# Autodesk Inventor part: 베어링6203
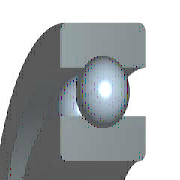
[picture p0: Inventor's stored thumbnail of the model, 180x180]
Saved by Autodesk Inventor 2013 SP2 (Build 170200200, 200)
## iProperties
IsCustomPart: 0
Company: 한국ATC센터
Created: 2014-12
Part Number: 베어링6203
Material: 강, 연강
Description: 깊은 그루브 볼 베어링
Document SubType Name: Modeling
Standard: KS B 2023
Designer: KYOUNG IL JANG
Standards Organization: KS
Language: ko-KR
Size Designation: 6203 - 17 x 40 x 12
Categories: <MemberInstance><Categories><Category DisplayName="샤프트 부품" InternalName="7f7aeb1f-a693-4053-b835-cee3144e0d98" Mnemonic="SHFT"><Category DisplayName="베어링" Inter
Density: 7.86 g/cm^3
Mass: 64.9809 g
Surface Area: 64.3582 cm^2
Volume: 8.26729 cm^3
Author: KYOUNG IL JANG
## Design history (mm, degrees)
sketch "스케치" dims "d0" = 5.98 (= -0.26 x WD + 0.26 x BD)
  geometry: L1 (3.01, 14.25)-(8.99, 14.25); L2 (6, 14.25)-(6, 11.26); L3 (6, 14.25)-(6, 17.24); L4 (3.778, 12.249)-(0, 12.249); L5 (0, 8.5)-(12, 8.5); L6 (3.778, 16.251)-(0, 16.251); L7 (0, 20)-(12, 20); L8 (12, 8.5)-(12, 12.249); L9 (8.222, 12.249)-(12, 12.249); L10 (8.222, 16.251)-(12, 16.251); L11 (12, 20)-(12, 16.251); L12 (-1.4, 0)-(8.4, 0) reference; L13 (0, -0.3)-(0, 5.3) reference
  constraints: 22 end point, 4 point on line, 2 collinear, 2 perpendicular, 2 symmetric about line, 1 midpoint, 1 parallel, 14 other
  dimensions: "d9" = 17 diameter of L5 L12 (= WD); "d11" = 40 diameter of L7 L12 (= BD); "d12" = 12 distance between parallel lines of L8 L13 (= KB); "d13" = 24.498 diameter of L9 L12 (= 0.326 x BD + 0.674 x WD)
revolve "본체" stored, may be unused: angle "d6" = 90 deg
revolve "볼" stored, may be unused: angle "d7" = 90 deg
pattern_circular "IDS_ARRAYBALL[SIMPL:T]" dims angle "d3" = 360 deg
body "Solid1"
fillet "모깎기1" dims "d1" = 0.6 (= KRS)
other parameters: "WD" = 17 [user parameter; used in 5 equation terms], "BD" = 40 [user parameter; used in 5 equation terms], "KB" = 12 [user parameter; used in 1 equation term], "KRS" = 0.6 [user parameter; used in 1 equation term], "d4" = 0, "d5" = 0, "d8" = 0, "d14" = 0, "d15" = 0, "BBA" = 0 [user parameter], "BC0" = 4750000 [user parameter], "BC" = 9560000 [user parameter], "WR" = 8.5 (= 0.5 x WD) [user parameter]
